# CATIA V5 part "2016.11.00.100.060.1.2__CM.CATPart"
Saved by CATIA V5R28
Part number: 2016.11.00.100.060.1.2__CM
Property "id_number": "2016.11.00.100.060.1.2"
Publications: "Absolute Axis System", "driver", "slider", "base", "cam diagram"
Bounding box of the stored display mesh (mm): x -60 to 210, y -87.5 to 87.5, z 0 to 260
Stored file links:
  N:\B2\Normteile\K\2016\11-14\010\cm\2016.11.00.100.060.1.2__CM.CATPart
  H:\CAD_Startmodelle\Tests\fill-in_PRT-SL_TEMPLATE.xlsx
  H:\CAD_Startmodelle\V5-R24\R24_TEMPLATE_PRT_FIBRO_CAM_TECNOLOGIES_INDEX.xlsx
  H:\z_Einordnen\170511__Anfrage_TK_HN\170511__CC01_TKHN.CATPart
  N:\B2\Normteile\K\2016\9xxx\2016.9024.1705.001\Entwurf_\170511__CC01_TKHN.CATPart
  N:\B2\Normteile\K\2016\9xxx\2016.9024.1707.006\Konstruktion\2016.9024.1707.006__HP__CUSTOMIZED_CAM_CM.CATPart
  N:\B2\Normteile\K\2016\9xxx\2016.9024.1707.005\Konstruktion\2016.9024.1707.005__HP__CUSTOMIZED_CAM_CM.CATPart
  N:\B2\Normteile\K\2016\9xxx\2016.9024.1707.008\Konstruktion\2016.9024.1707.008__HP__CUSTOMIZED_CAM_CM.CATPart
  N:\B2\Normteile\K\2016\9xxx\2016.9024.1707.009\Konstruktion\2016.9024.1707.009__HP__CUSTOMIZED_CAM_CM.CATPart
  N:\B2\Normteile\K\2016\9xxx\2016.9024.1707.010\Konstruktion\2016.9024.1707.010__HP__CUSTOMIZED_CAM_CM.CATPart
  N:\B2\Normteile\K\2016\9xxx\2016.9024.1708.002\Konstruktion\2016.9024.1708.002__HP__CUSTOMIZED_CAM_CM.CATPart
  N:\B2\Normteile\K\2016\9xxx\2016.9024.1802.001\Konstruktion\2016.9024.1802.001__HP__CUSTOMIZED_CAM_CM.CATPart
  N:\B2\Normteile\K\2016\9xxx\2016.9024.1802.002\Konstruktion\2016.9024.1802.002__HP__CUSTOMIZED_CAM_CM.CATPart
  N:\B2\Normteile\K\2016\9xxx\2016.9024.1811.003\Konstruktion\2016.9024.1811.003__HP__CUSTOMIZED_CAM_CM.CATPart
  N:\B2\Normteile\K\2016\9xxx\2016.9015.1811.001\Konstruktion\am\2016.9015.1811.001__AM__FCC_HV_DMC_0125-00.CATPart
  N:\B2\Normteile\K\2016\9xxx\2016.9024.1811.009\Konstruktion\2016.9024.1811.009__HP__CUSTOMIZED_CAM_CM.CATPart
  N:\B2\Normteile\K\2016\9xxx\2016.9024.1911.002\Konstruktion\am\2016.9024.1911.002__AM__CUSTOMIZED_CAM_CM.CATPart
  N:\B2\Normteile\K\2016\9xxx\2016.9024.2002.006\Konstruktion\2016.9024.2002.006__AM.CATPart
  N:\B2\Normteile\K\2016\9xxx\2016.9024.2004.001\Konstruktion\2016.9024.2004.001__AM__FCC_HV_CAEC_0260-45.CATPart
  N:\B2\Normteile\K\2016\9xxx\2016.9024.2006.002\Konstruktion\2016.9024.2006.002__AM__FCC_HV_CAEC_0260-40.CATPart
  N:\B2\Normteile\K\2016\9xxx\2016.9024.2006.005\Konstruktion\am\2016.9024.2006.005__AM__CFCC_HV_AEPC_0080-65.CATPart
  N:\B2\Normteile\K\2016\9xxx\2016.9024.2006.004\Konstruktion\am\2016.9024.2006.004__AM__CFCC_HV_AEC_0210-35.CATPart
  N:\B2\Normteile\K\2016\9xxx\2016.9026.2006.001\Konstruktion\am\2016.9026.2006.001__AM__FCC_LV_CAEC_0180-40.CATPart
  N:\B2\Normteile\K\2016\9xxx\2016.9015.2007.001\Konstruktion\am\2016.9015.2007.001__AM__FCC_HV_CDMPC_0090-00.CATPart
  N:\B2\Normteile\K\2016\9xxx\2016.9024.2005.001\Konstruktion\am\2016.9024.2005.001__AM__CFCC_HV_AEPC_1400-70.CATPart
  N:\B2\Normteile\K\2016\9xxx\2016.9024.2007.004\Konstruktion\am\2016.9024.2007.004__AM__CFCC_HV_AEC_1250-80.CATPart
  N:\B2\Normteile\K\2016\11-14\005\2016.11.00.052.040.1.02__AS__DIE_MOUNT_CAM__W52_A0_S40.CATProduct
  N:\B2\Normteile\K\2016\11-14\cm\005\catia\2016.11.00.052.025.1.2__CM.CATPart
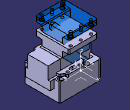
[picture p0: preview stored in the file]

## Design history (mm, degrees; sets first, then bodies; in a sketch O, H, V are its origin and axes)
Parameters
  group "process_parameters"
    modeltype = ""
    stocklist = ""
    id_number = "2016.11.00.100.060.1.2"
    id_number_rough_part = ""
    revision_index = ""
    revision_date = ""
    revision_description = ""
    category = ""
    material = ""
    manufacturing_information = ""
    standard = ""
  group "release_parameters_startmodel"
    sm_revision_index = "2016_00" {design table}
    sm_revision_date = "20.08.2016" {design table}
    sm_revision_name = "Meyer" {design table}
    sm_revision_description = "new part template FIBRO cam tecnologies" {design table}
AxisSystem1: origin (0, 0, 0), X (1, 0, 0), Y (0, 1, 0), Z (0, 0, 1)
Set1 "reference elements"
  Sketch1 "cam diagram" on ZX plane of AxisSystem1, origin (0, 0, 0), H (-1, 0, 0), V (0, 0, 1)
    line L1 (0, 0) -> (60, 0)
    line L2 (60, 0) -> (0, 60)
    point P2 (0, 60)
    line L3 (0, 60) -> (0, 0)
    length L1 = 60
    angle H L2 = 45
    horizontal: L1 H
    coincidence: P2 V
    vertical: L3 V
Body1 "finished_part" (main body)
  Body2 "rough_part"
  Add1 "rough_part": tool Body2
  Body3 "milling operations"
  Remove1 "milling operations": tool Body3
  Body4 "drilling operations"
  Remove2 "drilling operations": tool Body4
Body5 "driver"
  Solid1: solid without history
Body6 "slider"
  Solid2: solid without history
Body7 "base"
  Solid3: solid without history
Body8 "opened position"
  Body9 "slider"
    Body10 "slider"
      Solid4: linked copy from another document
    Assemble1: tool Body10
    Translate1: FirstPoint vertex [element of Sketch1 | element of Sketch1], SecondPoint vertex [element of Sketch1 | element of Sketch1], ToTransfor Assemble1
  Assemble2: tool Body9
  Body11 "driver"
    Body12 "driver"
      Solid5: linked copy from another document
    Assemble3: tool Body12
    Translate2: FirstPoint vertex [element of Sketch1 | element of Sketch1], SecondPoint vertex [element of Sketch1 | element of Sketch1], ToTransfor Assemble3
  Assemble4: tool Body11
